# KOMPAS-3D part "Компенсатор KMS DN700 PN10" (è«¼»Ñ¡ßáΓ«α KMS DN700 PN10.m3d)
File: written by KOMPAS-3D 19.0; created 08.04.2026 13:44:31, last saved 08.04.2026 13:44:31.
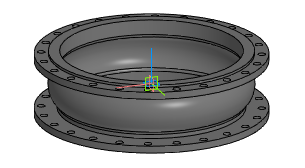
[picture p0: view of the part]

Document properties: Автор: Энергия; Полное имя файла: Z:\3.Личные\kachalov\3d для проектировщиков\7.1 Компенсатор\stp_Компенсатор KSM\Компенсатор KMS DN700 PN10.m3d

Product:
- Part/product: Компенсатор KMS DN700 PN10

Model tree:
1. Операция без истории:1  (labels: Компенсатор KMS DN700 PN10)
